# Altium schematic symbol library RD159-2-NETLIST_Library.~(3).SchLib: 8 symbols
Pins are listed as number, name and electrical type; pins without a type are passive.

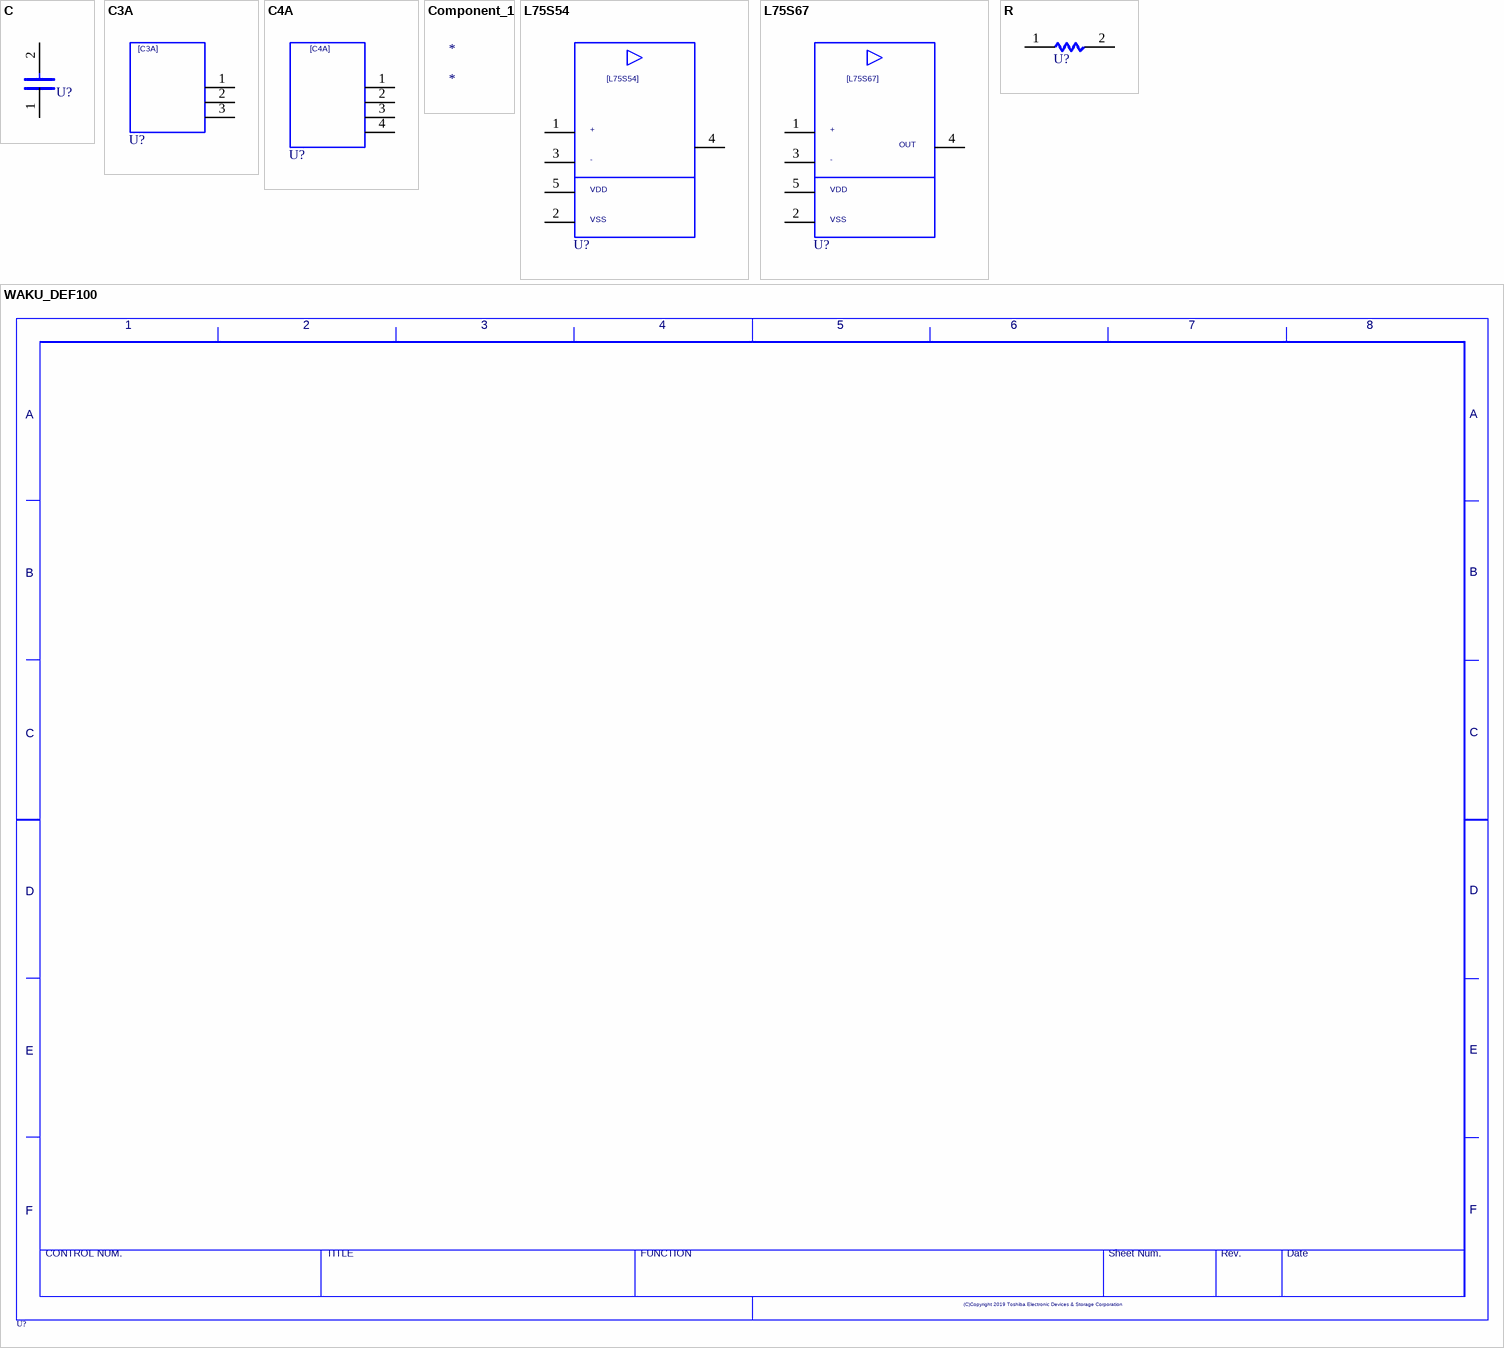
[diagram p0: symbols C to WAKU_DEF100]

## C
designator U?  (value not drawn)
OriginalSymbolOrigin: (2540,7620); Altium-Right: 20; Altium-Bottom: 10
pins: 1, 2

## C3A
designator U?  (value not drawn)
SAVEAREA0: -6798,-236,26764,20869; TIME: 09:53:04; UPDATEUSER: tomizawa-y; UPDATETIME: 09:53:12; SAVECOUNT: 2; OriginalSymbolOrigin: (2540,17780); Altium-Right: 50; Altium-Bottom: 60
pins: 1, 2, 3

## C4A
designator U?  (value not drawn)
SAVEAREA0: -8845,-265,28754,23475; SAVECOUNT: 22; TIME: 13:28:28; UPDATEUSER: tomizawa-y; UPDATETIME: 15:03:27; OriginalSymbolOrigin: (2540,20320); Altium-Right: 50; Altium-Bottom: 70
pins: 1, 2, 3, 4

## Component_1
designator *

## L75S54
designator U?  (value not drawn)
TIME: 16:27:13; UPDATEUSER: 19990028; UPDATETIME: 13:02:06; SAVECOUNT: 8; SAVEAREA0: -72307,-25685,103712,61936; OriginalSymbolOrigin: (5080,35560); Altium-Right: 80; Altium-Bottom: 130
pins: 1, 2, 3, 4, 5

## L75S67
designator U?  (value not drawn)
TIME: 16:27:13; UPDATEUSER: w90028dm; UPDATETIME: 15:17:13; SAVECOUNT: 13; SAVEAREA0: -43421,-10273,73920,48138; OriginalSymbolOrigin: (5080,35560); Altium-Right: 80; Altium-Bottom: 130
pins: 1, 2, 3, 4, 5

## R
designator U?  (value not drawn)
OriginalSymbolOrigin: (5080,5080); Altium-Right: 20
pins: 1, 2

## WAKU_DEF100
designator U?  (value not drawn)
PLOTTIME: HH:MM; SAVEAREA0: 198008,-65938,436964,90161; TIME: 14:30:25; UPDATEUSER: d5009410; UPDATETIME: 15:37:05; SAVECOUNT: 4; OriginalSymbolOrigin: (10160,284480); Altium-Right: 1570; Altium-Bottom: 1070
